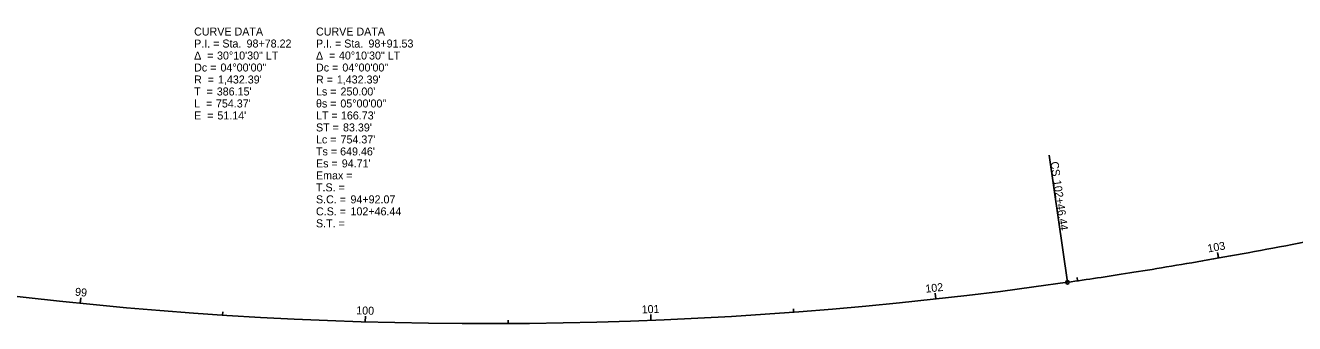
# Model space of a CAD drawing. Extents: x 1999336 to 2003366, y 252766 to 253936.
# Drawn here: x 2002477.2 to 2002921.4, y 252766.1 to 252870.6 of the extents above; entities that cross this region are included whole.
import ezdxf

# ---------------------------------------------------------------- set-up
doc = ezdxf.new("R2010")
doc.units = 0
for name, color, linetype in [('GE_X_CL_20', 7, 'Continuous'), ('GK_Visualization', 7, 'Continuous'), ('RW_X_Esmt_SH', 7, 'Continuous'), ('SC_Scratch3', 7, 'Continuous'), ('SV_X_Control_Cells_Found', 7, 'Continuous'), ('SV_X_Text_Elevation', 7, 'Continuous'), ('SV_X_Text_Name', 7, 'Continuous')]:
    doc.layers.add(name, color=color, linetype=linetype)

msp = doc.modelspace()

# ---------------------------------------------------------------- linework, layer by layer
at = {"layer": 'GE_X_CL_20'}
for p, q in [((2002841.92, 252780.58), (2002835.54, 252825.12)), ((2002894.8, 252789.09), (2002894.59, 252790.28)), ((2002496.4, 252773.2), (2002496.52, 252774.39)), ((2002795.85, 252774.74), (2002795.72, 252775.93)), ((2002596.17, 252766.74), (2002596.23, 252768.73)), ((2002696.15, 252767.25), (2002696.1, 252768.45))]:
    msp.add_line(p, q, dxfattribs=at)
msp.add_circle((2002841.92, 252780.58), 0.6, dxfattribs=at)
at = {"layer": 'GK_Visualization'}
msp.add_arc((2002638.78, 254198.49), 1432.39, 247.97811, 278.15308, dxfattribs=at)
msp.add_arc((2002638.78, 254198.49), 1432.39, 247.97811, 278.15308, dxfattribs=at)
msp.add_open_spline([(2002841.92, 252780.58), (2002848.79, 252781.56), (2002862.53, 252783.63), (2002889.94, 252788.14), (2002924.09, 252794.39), (2002964.93, 252802.69), (2003005.63, 252811.58), (2003039.48, 252819.32), (2003066.54, 252825.61), (2003080.07, 252828.77), (2003086.83, 252830.35)], degree=3, dxfattribs=at)
msp.add_open_spline([(2002841.92, 252780.58), (2002848.79, 252781.56), (2002862.53, 252783.63), (2002889.94, 252788.14), (2002924.09, 252794.39), (2002964.93, 252802.69), (2003005.63, 252811.58), (2003039.48, 252819.32), (2003066.54, 252825.61), (2003080.07, 252828.77), (2003086.83, 252830.35)], degree=3, dxfattribs=at)
at = {"layer": 'SC_Scratch3'}
for p, q in [((2002841.92, 252780.58), (2002835.54, 252825.12)), ((2002894.8, 252789.09), (2002894.45, 252791.06)), ((2002845.44, 252781.09), (2002845.27, 252782.28)), ((2002795.85, 252774.74), (2002795.63, 252776.73)), ((2002496.4, 252773.2), (2002496.6, 252775.19)), ((2002546.23, 252769.09), (2002546.31, 252770.29)), ((2002596.17, 252766.74), (2002596.23, 252768.73)), ((2002696.15, 252767.25), (2002696.07, 252769.25)), ((2002746.07, 252770.13), (2002745.98, 252771.32)), ((2002646.17, 252766.12), (2002646.16, 252767.32))]:
    msp.add_line(p, q, dxfattribs=at)
msp.add_circle((2002841.92, 252780.58), 0.6, dxfattribs=at)
at = {"layer": 'SV_X_Text_Name'}
for p, q in [((2002841.92, 252780.58), (2002835.54, 252825.12)), ((2002596.17, 252766.74), (2002596.23, 252768.73))]:
    msp.add_line(p, q, dxfattribs=at)
msp.add_circle((2002841.92, 252780.58), 0.6, dxfattribs=at)

# ---------------------------------------------------------------- texts
at = {"layer": 'GE_X_CL_20'}
for s, rotation, p in [('CS', 278.1531, (2002835.93, 252822.69)), ('102+46.44', 278.1531, (2002836.86, 252816.23)), ('100', 358.2955, (2002592.97, 252769.38))]:
    msp.add_text(s, height=2.8, rotation=rotation, dxfattribs=at).set_placement(p)
at = {"layer": 'RW_X_Esmt_SH'}
for s, p in [('CURVE DATA', (2002536.27, 252867.04)), ('P.I. = Sta. ', (2002536.27, 252862.84)), ('98+78.22', (2002554.63, 252862.84)), ('CURVE DATA', (2002578.92, 252867.04)), ('P.I. = Sta. ', (2002578.92, 252862.84)), ('98+91.53', (2002597.29, 252862.84)), ('Δ  = ', (2002536.27, 252858.64)), ('30°10\'30" LT', (2002544.29, 252858.64)), ('Δ  = ', (2002578.92, 252858.64)), ('40°10\'30" LT', (2002586.95, 252858.64)), ('Dc = ', (2002536.27, 252854.44)), ('04°00\'00"', (2002545.5, 252854.44)), ('Dc = ', (2002578.92, 252854.44)), ('04°00\'00"', (2002588.16, 252854.44)), ('R  = ', (2002536.27, 252850.24)), ("1,432.39'", (2002544.63, 252850.24)), ('R = ', (2002578.92, 252850.24)), ("1,432.39'", (2002586.21, 252850.24)), ('T  = ', (2002536.27, 252846.04)), ("386.15'", (2002544.2, 252846.04)), ('Ls = ', (2002578.92, 252846.04)), ("250.00'", (2002587.51, 252846.04)), ('L  = ', (2002536.27, 252841.84)), ("754.37'", (2002543.91, 252841.84)), ('θs = ', (2002578.92, 252841.84)), ('05°00\'00"', (2002587.46, 252841.84)), ('E  = ', (2002536.27, 252837.64)), ("51.14'", (2002544.42, 252837.64)), ('LT = ', (2002578.92, 252837.64)), ("166.73'", (2002587.65, 252837.64)), ('ST = ', (2002578.92, 252833.44)), ("83.39'", (2002588.38, 252833.44)), ('Lc = ', (2002578.92, 252829.24)), ("754.37'", (2002587.51, 252829.24)), ('Ts = ', (2002578.92, 252825.04)), ("649.46'", (2002587.37, 252825.04)), ('Es = ', (2002578.92, 252820.84)), ("94.71'", (2002587.95, 252820.84)), ('Emax = ', (2002578.92, 252816.64)), ('T.S. = ', (2002578.92, 252812.44)), ('S.C. = ', (2002578.92, 252808.24)), ('94+92.07', (2002590.99, 252808.24)), ('C.S. = ', (2002578.92, 252804.04)), ('102+46.44', (2002590.99, 252804.04)), ('S.T. = ', (2002578.92, 252799.84))]:
    msp.add_text(s, height=2.8, dxfattribs=at).set_placement(p)
at = {"layer": 'SC_Scratch3'}
for s, rotation, p in [('CS', 278.1531, (2002835.93, 252822.69)), ('102+46.44', 278.1531, (2002836.86, 252816.23)), ('103', 10.066, (2002891.14, 252791.03)), ('99', 354.2955, (2002494.5, 252775.94)), ('102', 6.2955, (2002792.32, 252776.91)), ('101', 2.2955, (2002692.94, 252769.67)), ('100', 358.2955, (2002592.97, 252769.38))]:
    msp.add_text(s, height=2.8, rotation=rotation, dxfattribs=at).set_placement(p)
at = {"layer": 'SV_X_Control_Cells_Found'}
for s, p in [('CURVE DATA', (2002536.27, 252867.04)), ('P.I. = Sta. ', (2002536.27, 252862.84)), ('98+78.22', (2002554.63, 252862.84)), ('CURVE DATA', (2002578.92, 252867.04)), ('P.I. = Sta. ', (2002578.92, 252862.84)), ('98+91.53', (2002597.29, 252862.84)), ('Δ  = ', (2002536.27, 252858.64)), ('30°10\'30" LT', (2002544.29, 252858.64)), ('Δ  = ', (2002578.92, 252858.64)), ('40°10\'30" LT', (2002586.95, 252858.64)), ('Dc = ', (2002536.27, 252854.44)), ('04°00\'00"', (2002545.5, 252854.44)), ('Dc = ', (2002578.92, 252854.44)), ('04°00\'00"', (2002588.16, 252854.44)), ('R  = ', (2002536.27, 252850.24)), ("1,432.39'", (2002544.63, 252850.24)), ('R = ', (2002578.92, 252850.24)), ("1,432.39'", (2002586.21, 252850.24)), ('T  = ', (2002536.27, 252846.04)), ("386.15'", (2002544.2, 252846.04)), ('Ls = ', (2002578.92, 252846.04)), ("250.00'", (2002587.51, 252846.04)), ('L  = ', (2002536.27, 252841.84)), ("754.37'", (2002543.91, 252841.84)), ('θs = ', (2002578.92, 252841.84)), ('05°00\'00"', (2002587.46, 252841.84)), ('E  = ', (2002536.27, 252837.64)), ("51.14'", (2002544.42, 252837.64)), ('LT = ', (2002578.92, 252837.64)), ("166.73'", (2002587.65, 252837.64)), ('ST = ', (2002578.92, 252833.44)), ("83.39'", (2002588.38, 252833.44)), ('Lc = ', (2002578.92, 252829.24)), ("754.37'", (2002587.51, 252829.24)), ('Ts = ', (2002578.92, 252825.04)), ("649.46'", (2002587.37, 252825.04)), ('Es = ', (2002578.92, 252820.84)), ("94.71'", (2002587.95, 252820.84)), ('Emax = ', (2002578.92, 252816.64)), ('T.S. = ', (2002578.92, 252812.44)), ('S.C. = ', (2002578.92, 252808.24)), ('94+92.07', (2002590.99, 252808.24)), ('C.S. = ', (2002578.92, 252804.04)), ('102+46.44', (2002590.99, 252804.04)), ('S.T. = ', (2002578.92, 252799.84))]:
    msp.add_text(s, height=2.8, dxfattribs=at).set_placement(p)
at = {"layer": 'SV_X_Text_Elevation'}
for s, p in [('CURVE DATA', (2002536.27, 252867.04)), ('P.I. = Sta. ', (2002536.27, 252862.84)), ('98+78.22', (2002554.63, 252862.84)), ('CURVE DATA', (2002578.92, 252867.04)), ('P.I. = Sta. ', (2002578.92, 252862.84)), ('98+91.53', (2002597.29, 252862.84)), ('Δ  = ', (2002536.27, 252858.64)), ('30°10\'30" LT', (2002544.29, 252858.64)), ('Δ  = ', (2002578.92, 252858.64)), ('40°10\'30" LT', (2002586.95, 252858.64)), ('Dc = ', (2002536.27, 252854.44)), ('04°00\'00"', (2002545.5, 252854.44)), ('Dc = ', (2002578.92, 252854.44)), ('04°00\'00"', (2002588.16, 252854.44)), ('R  = ', (2002536.27, 252850.24)), ("1,432.39'", (2002544.63, 252850.24)), ('R = ', (2002578.92, 252850.24)), ("1,432.39'", (2002586.21, 252850.24)), ('T  = ', (2002536.27, 252846.04)), ("386.15'", (2002544.2, 252846.04)), ('Ls = ', (2002578.92, 252846.04)), ("250.00'", (2002587.51, 252846.04)), ('L  = ', (2002536.27, 252841.84)), ("754.37'", (2002543.91, 252841.84)), ('θs = ', (2002578.92, 252841.84)), ('05°00\'00"', (2002587.46, 252841.84)), ('E  = ', (2002536.27, 252837.64)), ("51.14'", (2002544.42, 252837.64)), ('LT = ', (2002578.92, 252837.64)), ("166.73'", (2002587.65, 252837.64)), ('ST = ', (2002578.92, 252833.44)), ("83.39'", (2002588.38, 252833.44)), ('Lc = ', (2002578.92, 252829.24)), ("754.37'", (2002587.51, 252829.24)), ('Ts = ', (2002578.92, 252825.04)), ("649.46'", (2002587.37, 252825.04)), ('Es = ', (2002578.92, 252820.84)), ("94.71'", (2002587.95, 252820.84)), ('Emax = ', (2002578.92, 252816.64)), ('T.S. = ', (2002578.92, 252812.44)), ('S.C. = ', (2002578.92, 252808.24)), ('94+92.07', (2002590.99, 252808.24)), ('C.S. = ', (2002578.92, 252804.04)), ('102+46.44', (2002590.99, 252804.04)), ('S.T. = ', (2002578.92, 252799.84))]:
    msp.add_text(s, height=2.8, dxfattribs=at).set_placement(p)
at = {"layer": 'SV_X_Text_Name'}
for s, rotation, p in [('CS', 278.1531, (2002835.93, 252822.69)), ('102+46.44', 278.1531, (2002836.86, 252816.23)), ('100', 358.2955, (2002592.97, 252769.38))]:
    msp.add_text(s, height=2.8, rotation=rotation, dxfattribs=at).set_placement(p)

doc.saveas('drawing.dxf')
